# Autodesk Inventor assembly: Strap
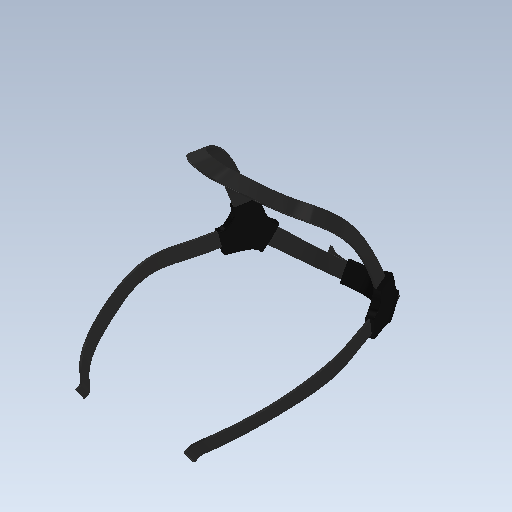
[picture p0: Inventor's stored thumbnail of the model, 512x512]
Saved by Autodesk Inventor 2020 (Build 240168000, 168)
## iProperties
Created: 2021-10
Part Number: Strap
Document SubType Name: Assembly
Designer: bruno
Author: bruno
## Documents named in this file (5)
- K:\STI2D\IT\P2 Indicateur directionnel\Inventor\Inventor indicateur directionnel\Casque\Strap.iam
- K:\STI2D\IT\P2 Indicateur directionnel\Inventor\Inventor indicateur directionnel\Casque\strap clips.ipt
- K:\STI2D\IT\P2 Indicateur directionnel\Inventor\Inventor indicateur directionnel\Casque\Strap 15mm.ipt
- K:\STI2D\IT\P2 Indicateur directionnel\Inventor\Inventor indicateur directionnel\Casque\Buckle.ipt
- K:\STI2D\IT\P2 Indicateur directionnel\Inventor\Inventor indicateur directionnel\Casque\Pièce12.ipt
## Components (4 placed, 4 different names)
1. strap clips:1
2. Strap 15mm:1
3. Buckle:1
4. Pièce12
